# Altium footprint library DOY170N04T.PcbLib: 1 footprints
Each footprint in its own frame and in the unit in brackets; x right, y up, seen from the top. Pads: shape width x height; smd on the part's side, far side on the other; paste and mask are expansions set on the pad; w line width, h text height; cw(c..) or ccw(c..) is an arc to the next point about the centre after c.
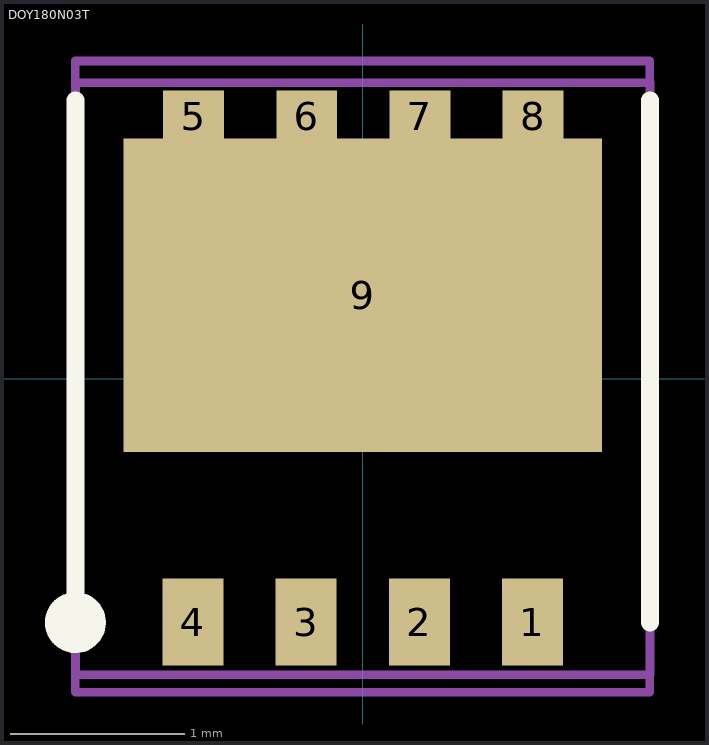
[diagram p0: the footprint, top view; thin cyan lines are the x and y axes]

## DOY180N03T [mm]
pads (9):
  rect 0.35x0.5 smd: 1(0.975,-1.397) 2(0.325,-1.397) 3(-0.325,-1.397) 4(-0.975,-1.397)
  rect 0.35x0.3 smd: 5(-0.971,1.507) 6(-0.321,1.507) 7(0.329,1.507) 8(0.979,1.507)
  rect 2.75x1.8 smd: 9(0,0.48)
Top Overlay:
  circle w0.15: c-1.65,-1.4 r0.1
  lines w0.102: -1.65,-1.4 -1.65,1.6 ; 1.65,-1.4 1.65,1.6
Mechanical 1:
  lines w0.05: -1.65,-1.7 1.65,-1.7 1.65,1.7 -1.65,1.7 -1.65,-1.7
Top Courtyard:
  lines w0.05: -1.651,-1.8 -1.651,1.825 1.649,1.825 1.649,-1.8 -1.651,-1.8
